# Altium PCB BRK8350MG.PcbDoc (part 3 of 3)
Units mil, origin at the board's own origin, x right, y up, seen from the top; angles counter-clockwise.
Board outline 8858.27 x 5511.81 mil, 6 copper layers (L1-TOP, L2-GND, L3-PWR, L4-PWR, L5-GND, L6-BOT), stack 81.526 mil thick; 49 components, 350 nets, 1087 pads, 250 vias.
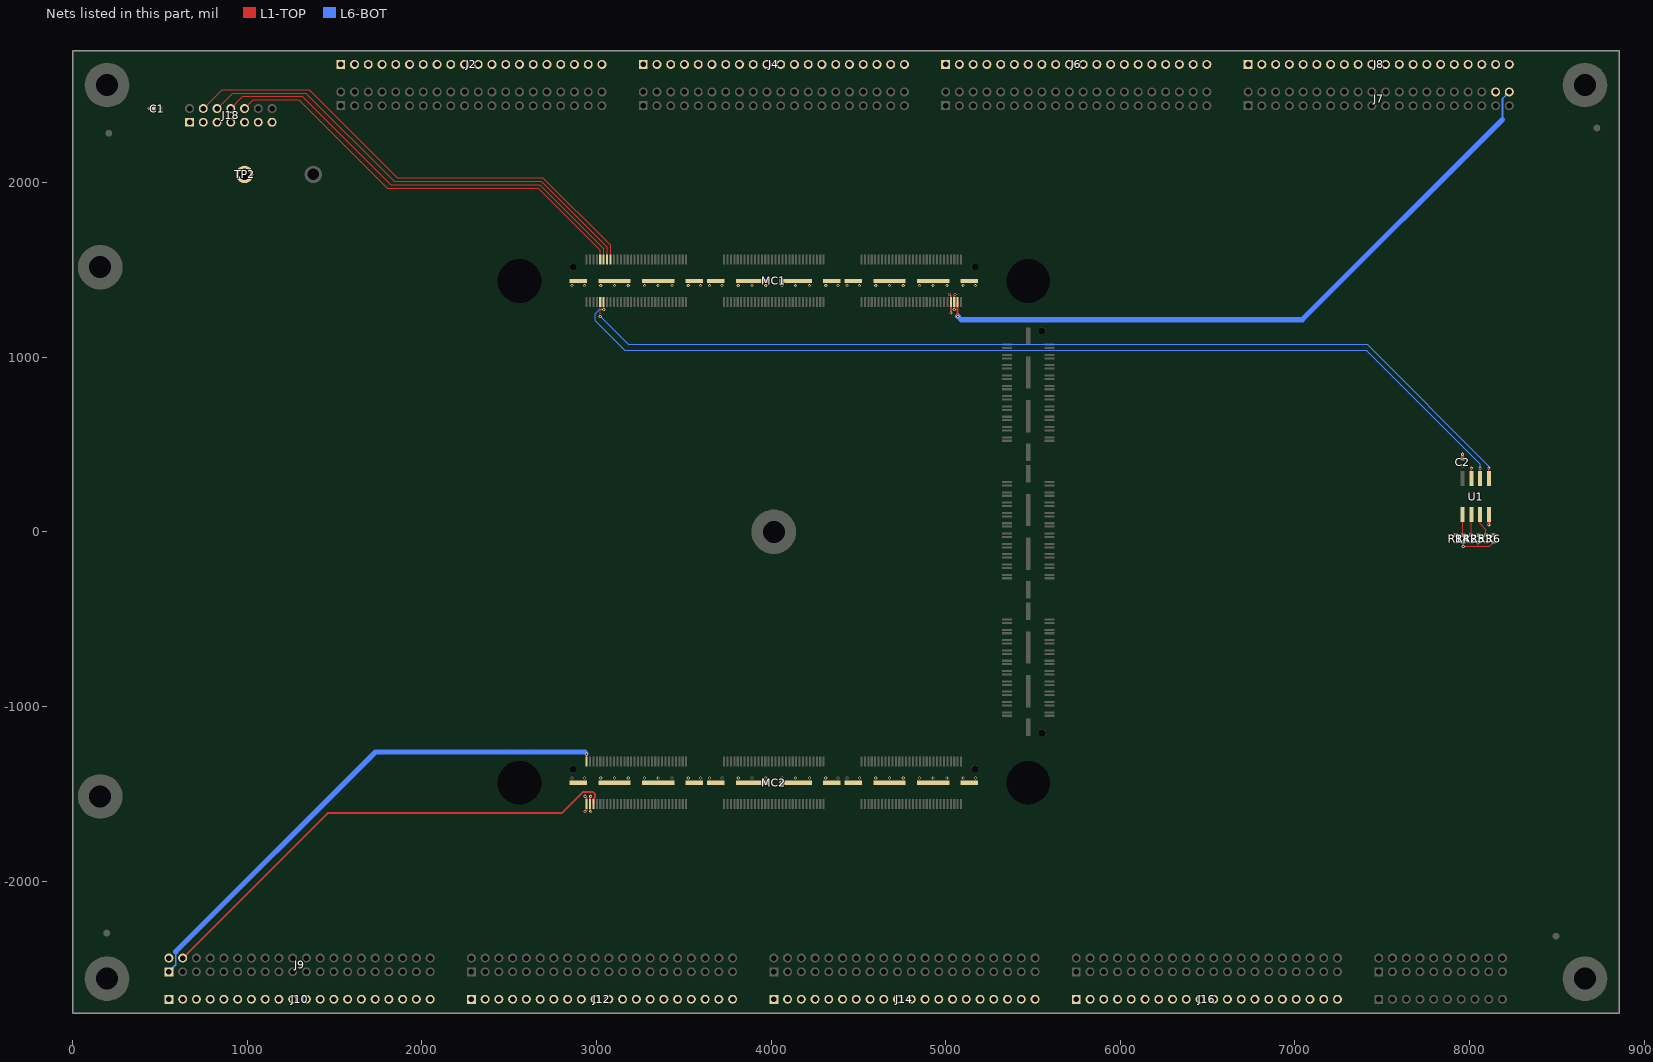
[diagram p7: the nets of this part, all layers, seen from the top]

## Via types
v1: diameter 18, hole 10, L1-TOP to L6-BOT, tented both sides, 250 vias

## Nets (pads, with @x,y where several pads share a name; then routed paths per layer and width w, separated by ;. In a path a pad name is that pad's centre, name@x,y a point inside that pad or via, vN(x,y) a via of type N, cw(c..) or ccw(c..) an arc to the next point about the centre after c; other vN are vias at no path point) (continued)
DGND: C1.1 C2.1 J2.1 J2.2 J2.3 J2.4 J2.5 J2.6 J2.7 J2.8 J2.9 J2.10 J2.11 J2.12 J2.13 J2.14 J2.15 J2.16 J2.17 J2.18 J2.19 J2.20 J4.1 J4.2 J4.3 J4.4 J4.5 J4.6 J4.7 J4.8 J4.9 J4.10 J4.11 J4.12 J4.13 J4.14 J4.15 J4.16 J4.17 J4.18 J4.19 J4.20 J6.1 J6.2 J6.3 J6.4 J6.5 J6.6 J6.7 J6.8 J6.9 J6.10 J6.11 J6.12 J6.13 J6.14 J6.15 J6.16 J6.17 J6.18 J6.19 J6.20 J8.1 J8.2 J8.3 J8.4 J8.5 J8.6 J8.7 J8.8 J8.9 J8.10 J8.11 J8.12 J8.13 J8.14 J8.15 J8.16 J8.17 J8.18 J8.19 J8.20 J10.1 J10.2 J10.3 J10.4 J10.5 J10.6 J10.7 J10.8 J10.9 J10.10 J10.11 J10.12 J10.13 J10.14 J10.15 J10.16 J10.17 J10.18 J10.19 J10.20 J12.1 J12.2 J12.3 J12.4 J12.5 J12.6 J12.7 J12.8 J12.9 J12.10 J12.11 J12.12 J12.13 J12.14 J12.15 J12.16 J12.17 J12.18 J12.19 J12.20 J14.1 J14.2 J14.3 J14.4 J14.5 J14.6 J14.7 J14.8 J14.9 J14.10 J14.11 J14.12 J14.13 J14.14 J14.15 J14.16 J14.17 J14.18 J14.19 J14.20 J16.1 J16.2 J16.3 J16.4 J16.5 J16.6 J16.7 J16.8 J16.9 J16.10 J16.11 J16.12 J16.13 J16.14 J16.15 J16.16 J16.17 J16.18 J16.19 J16.20 J18.1@669.29,2345.94 J18.3@748.03,2345.94 J18.5@826.77,2345.94 J18.7@905.51,2345.94 J18.9@984.25,2345.94 J18.11 J18.13 MC1.0 MC2.0 R4.1 R5.1 R6.1 TP2.1 U1.4 U1.7 | length 403.6
  L1-TOP w5: v1(7964.53,-83.17) 8051,-83.17 ; U1.7@8010.96,304.78 v1(8010.96,364.78) ; R5.1@8051.14,-58.17 8051.14,-83.03 8051,-83.17 ; R6.1@8137.76,-58.17 8112.76,-83.17 8051,-83.17
  L1-TOP w11: v1(438.57,2424.44) C1.1@463.57,2424.44 ; v1(7964.53,-83.17) R4.1@7964.53,-58.17
  L1-TOP w18: C2.1@7961,419.16 v1(7961,444.16) ; v1(8110.96,40.06) U1.4@8110.96,100.06
  other v1: 2860.45,-1409.99 2931.31,-1409.99 3024.62,-1409.99 3103.36,-1409.99 3182.1,-1409.99 3274.62,-1409.99 3353.36,-1409.99 3432.1,-1409.99 3525.41,-1409.99 3596.28,-1409.99 3647.85,-1409.99 3718.72,-1409.99 3812.02,-1409.99 3890.76,-1409.99 3969.5,-1409.99 4062.02,-1409.99 4140.76,-1409.99 4219.5,-1409.99 4312.81,-1409.99 4383.68,-1409.99 4435.25,-1409.99 4506.12,-1409.99 4599.43,-1409.99 4678.17,-1409.99 4756.91,-1409.99 4849.43,-1409.99 4928.17,-1409.99 5006.91,-1409.99 5100.21,-1409.99 5171.08,-1409.99 2860.45,1410.02 2931.31,1410.02 3024.62,1410.02 3103.36,1410.02 3182.1,1410.02 3274.62,1410.02 3353.36,1410.02 3432.1,1410.02 3525.41,1410.02 3596.28,1410.02 3647.85,1410.02 3718.72,1410.02 3812.02,1410.02 3890.76,1410.02 3969.5,1410.02 4062.02,1410.02 4140.76,1410.02 4219.5,1410.02 4312.81,1410.02 4383.68,1410.02 4435.25,1410.02 4506.12,1410.02 4599.43,1410.02 4678.17,1410.02 4756.91,1410.02 4849.43,1410.02 4928.17,1410.02 5006.91,1410.02 5100.21,1410.02 5171.08,1410.02
FPGA_JTAG_TCK: J18.6@826.77,2424.69 MC1.13 | length 2708.7
  L1-TOP w5: J18.6@826.77,2424.69 915.35,2513.27 1335.16,2513.27 1840.55,2007.87 2684.13,2007.87 3061.04,1630.96 MC1.13@3061.04,1558.68
FPGA_JTAG_TDI: J18.10@984.25,2424.69 MC1.9 | length 2469.5
  L1-TOP w5: J18.10@984.25,2424.69 1033.46,2473.9 1295.79,2473.9 1801.18,1968.5 2667.5,1968.5 3021.67,1614.33 MC1.9@3021.67,1558.68
FPGA_JTAG_TDO: J18.8@905.51,2424.69 MC1.11 | length 2589.1
  L1-TOP w5: J18.8@905.51,2424.69 974.41,2493.58 1315.47,2493.58 1820.87,1988.19 2675.81,1988.19 3041.35,1622.65 MC1.11@3041.35,1558.68
FPGA_JTAG_TMS: J18.4@748.03,2424.69 MC1.15 | length 2828.9
  L1-TOP w5: J18.4@748.03,2424.69 856.3,2532.95 1354.84,2532.95 1860.24,2027.56 2693.44,2027.56 3080.72,1640.28 MC1.15@3080.72,1558.68
I2C_SCL: MC1.12 U1.6 | length 5629.4
  L1-TOP w5: v1(3041.35,1273.37) MC1.12@3041.35,1313.37 ; U1.6@8060.96,304.78 v1(8060.96,364.78)
  L6-BOT w5: v1@3041.35,1275.37 3019.37,1275.37 2993,1249 2993,1210 3163,1040 7408,1040 8060.96,387.04 v1(8060.96,364.78)
I2C_SDA: MC1.10 U1.5 | length 5597.1
  L1-TOP w5: v1(3021.67,1233.37) MC1.10@3021.67,1313.37 ; U1.5@8110.96,304.78 v1(8110.96,364.78)
  L6-BOT w5: v1@3021.67,1235.37 3183.04,1074 7414,1074 8110.96,377.04 v1(8110.96,364.78)
NetR1_1: R1.1 R4.2 U1.1 | length 163.6
  L1-TOP w5: R1.1@7921.22,-18.8 R4.2@7964.53,-18.8 7960.96,-15.24 U1.1@7960.96,100.06
NetR2_1: R2.1 R5.2 U1.2 | length 163.5
  L1-TOP w5: U1.2@8010.96,100.06 8010.96,-15.68 R2.1@8007.83,-18.8 R5.2@8051.14,-18.8
NetR3_1: R3.1 R6.2 U1.3 | length 176
  L1-TOP w5: U1.3@8060.96,100.06 8060.96,45.04 8094.45,11.55 R3.1@8094.45,-18.8 R6.2@8137.76,-18.8
VCCBATT: J9.4 MC2.6 | length 2822.4
  L1-TOP w11: J9.4@629.92,-2440.94 1459.87,-1611 2801,-1611 2923,-1489 2979,-1489 2992,-1502 2992,-1519 2982.3,-1528.7 MC2.6@2982.3,-1558.65
VIO1: J7.38 MC1.174 MC1.176 | length 194.6
  L1-TOP w10: v1(5021.54,1359.37) 5029.54,1351.37 MC1.174@5029.54,1315.37 ; MC1.176@5049.23,1315.37 5049.23,1351.37 v1@5057.23,1359.37
  L1-TOP w11: v1(5029.54,1253.37) MC1.174@5029.54,1313.37 ; v1(5049.23,1273.37) MC1.176@5049.23,1313.37
  other v1: 5053.29,1359.37
VIO2: J9.2 MC2.2 MC2.4 | length 189.3
  L1-TOP w10: v1(2934.93,-1602.65) 2942.93,-1594.65 MC2.2@2942.93,-1558.65 2942.93,-1522.65 v1(2934.93,-1514.65) ; v1@2970.61,-1602.65 2962.61,-1594.65 MC2.4@2962.61,-1558.65 2962.61,-1522.65 v1@2970.61,-1514.65
  other v1: 2966.68,-1602.65 2966.68,-1514.65
VREF1: J7.40 MC1.178 | length 3857.5
  L1-TOP w11: v1(5068.91,1233.37) MC1.178@5068.91,1313.37
  L6-BOT w10: 8188.98,2362.2 8188.98,2480.31 J7.40@8228.35,2519.69
  L6-BOT w30: v1@5068.91,1235.37 5089.28,1215 7041.77,1215 8188.98,2362.2
VREF2: J9.1 MC2.1 | length 3005.2
  L1-TOP w5: MC2.1@2942.93,-1313.34 v1(2942.93,-1273.34)
  L6-BOT w10: J9.1@551.18,-2519.69 590.55,-2480.32 590.55,-2404.45
  L6-BOT w20: 2935,-1261 2942.93,-1268.93 v1(2942.93,-1273.34)
  L6-BOT w30: 590.55,-2404.45 1734,-1261 2935,-1261
pads on no net: FID1.FID? FID2.FID? FID3.FID? FID4.FID? J9.6 J18.1@7480.31,-2677.17 J18.2@7559.06,-2677.17 J18.3@7637.8,-2677.17 J18.4@7716.54,-2677.17 J18.5@7795.28,-2677.17 J18.6@7874.02,-2677.17 J18.7@7952.76,-2677.17 J18.8@8031.5,-2677.17 J18.9@8110.24,-2677.17 J18.10@8188.98,-2677.17 J18.12 J18.14 JSO1.1 JSO2.1 JSO3.1 JSO4.1 MC1.14 MC1.16 MC1.180 MC1.MH MC2.MH MC3.0 MC3.1 MC3.2 MC3.3 MC3.4 MC3.5 MC3.6 MC3.7 MC3.8 MC3.9 MC3.10 MC3.11 MC3.12 MC3.13 MC3.14 MC3.15 MC3.16 MC3.17 MC3.18 MC3.19 MC3.20 MC3.21 MC3.22 MC3.23 MC3.24 MC3.25 MC3.26 MC3.27 MC3.28 MC3.29 MC3.30 MC3.31 MC3.32 MC3.33 MC3.34 MC3.35 MC3.36 MC3.37 MC3.38 MC3.39 MC3.40 MC3.41 MC3.42 MC3.43 MC3.44 MC3.45 MC3.46 MC3.47 MC3.48 MC3.49 MC3.50 MC3.51 MC3.52 MC3.53 MC3.54 MC3.55 MC3.56 MC3.57 MC3.58 MC3.59 MC3.60 MC3.61 MC3.62 MC3.63 MC3.64 MC3.65 MC3.66 MC3.67 MC3.68 MC3.69 MC3.70 MC3.71 MC3.72 MC3.73 MC3.74 MC3.75 MC3.76 MC3.77 MC3.78 MC3.79 MC3.80 MC3.81 MC3.82 MC3.83 MC3.84 MC3.85 MC3.86 MC3.87 MC3.88 MC3.89 MC3.90 MC3.91 MC3.92 MC3.93 MC3.94 MC3.95 MC3.96 MC3.97 MC3.98 MC3.99 MC3.100 MC3.101 MC3.102 MC3.103 MC3.104 MC3.105 MC3.106 MC3.107 MC3.108 MC3.109 MC3.110 MC3.111 MC3.112 MC3.113 MC3.114 MC3.115 MC3.116 MC3.117 MC3.118 MC3.119 MC3.120 MC3.MH MH1.1 MH2.1 MH3.1 MH4.1 MH5.1 MH6.1

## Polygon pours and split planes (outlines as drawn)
+VDCIN on L1-TOP "L1_+VDCIN" (solid, pour order 221): 374,2244.09 374,354.33 3010,354.33 3010,1601 2681.87,1929.13 1771.65,1929.13 1456.69,2244.09
+3.3VDD on L1-TOP "L1_+3.3VDD" (solid, pour order 230): 5020,1615 5039,1634 7322,1634 8101,2413 8101,2602 8356,2602 8669,2289 8669,354.33 5112,354.33 5112,1359 5078,1359 5020,1417
VIO2 on L4-PWR "L4_VIO2" (solid, pour order 227): 39.37,-2716.54 4409.45,-2716.54 4409.45,2716.54 39.37,2716.54
VIO1 on L4-PWR "L4_VIO1" (solid, pour order 225): 8818.9,2716.54 4448.82,2716.54 4448.82,-2716.54 8818.9,-2716.54
DGND on L5-GND "L4-DGND" (solid, pour order 202): 19.68,-2736.22 19.68,2736.22 8838.58,2736.22 8838.58,-2736.22
DGND on L2-GND "L2_DGND" (solid, pour order 220): 19.69,-2736.22 19.69,2736.22 8838.58,2736.22 8838.58,-2736.22
+1.8VDD on L3-PWR "L3_+1.8VDD" (solid, pour order 224): 39.37,2716.54 39.37,-2716.54 8818.9,-2716.54 8818.9,2716.54

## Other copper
L1-TOP:
  rectangle net DGND: 2846,1400 2945,1448
  rectangle net DGND: 3012,1400 5185,1449
  rectangle net DGND: 2846,-1449 5185,-1400

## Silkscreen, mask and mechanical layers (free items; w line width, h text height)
Top Silkscreen:
  lines w4.72: 6167.63,1300.63 6167.7,1300.63
  lines w7.87: 413.39,-1673.23 5708.68,-1673.21 5708.68,1673.24 413.39,1673.23
  text "2:Vref" at 651.7,2730.24 h40 r270
  text "4:TMS" at 729.7,2730.24 h40 r270
  text "6:TCK" at 808.7,2730.24 h40 r270
  text "8:TDO" at 885.7,2730.24 h40 r270
  text "10:TDI" at 964.7,2730.24 h40 r270
  text "DGND" at 1362.65,2665.41 h30
  text "DGND" at 3094.93,2665.41 h30
  text "DGND" at 4827.22,2665.41 h30
  text "DGND" at 6559.5,2665.41 h30
  text "DGND" at 8287.22,2663.47 h30
  text "'.Part_Number' / '.PCB_Revision'XX" at 6913.7,-57.76 h40
  text "DGND" at 378.4,-2688.92 h30
  text "DGND" at 2110.68,-2688.92 h30
  text "DGND" at 3842.97,-2688.92 h30
  text "DGND" at 5575.25,-2688.92 h30
  text "DGND" at 7306.22,-2693.97 h30
  text "DGND" at 8247.22,-2693.97 h30
Dimensions:
  text ":::" at 2778.52,2835 h50 r180
  text ":::" at 6154.52,2806 h50
  text ":::" at 8920,1240 h50 r270
  text ":::" at -41,1148.36 h50 r90
  text ":::" at 8926,-1158 h50 r270
  text ":::" at -53,-1222 h50 r90
  text ":::" at 6246.16,-2793 h50 r180
  text ":::" at 2778.52,-2807 h50 r180
Outline:
  the board outline again, w8
Fab Notes:
  drawing of 56 lines, arcs and shapes, not listed
  text "LAYER STACK TABLE" at 5597,6144 h60
  text "M" at 9000.2,6000.12 h91.75
  text "a" at 9061.4,6000.12 h91.75
  text "t" at 9105.92,6000.12 h91.75
  text "e" at 9128.17,6000.12 h91.75
  text "r" at 9172.69,6000.12 h91.75
  text "i" at 9200.51,6000.12 h91.75
  text "a" at 9217.2,6000.12 h91.75
  text "l" at 9261.71,6000.12 h91.75
  text "C" at 9428.48,5896.05 h97.15
  text "o" at 9472.99,5896.05 h97.15
  text "p" at 9517.51,5896.04 h97.15
  text "p" at 9562.02,5896.04 h97.15
  text "e" at 9606.53,5896.05 h97.15
  text "r" at 9651.04,5896.05 h97.15
  text "P" at 8983.51,5894.41 h91.75
  text "r" at 9039.15,5894.41 h91.75
  text "e" at 9066.97,5894.41 h91.75
  text "s" at 9111.49,5894.41 h91.75
  text "s" at 9156,5894.41 h91.75
  text "e" at 9200.51,5894.41 h91.75
  text "d" at 9245.02,5894.41 h91.75
  text "G" at 6680.8,5788.69 h91.75
  text "e" at 6742,5788.69 h91.75
  text "r" at 6786.51,5788.69 h91.75
  text "b" at 6814.33,5788.69 h91.75
  text "e" at 6858.85,5788.69 h91.75
  text "r" at 6903.36,5788.69 h91.75
  text "M" at 8499.61,5788.69 h91.75
  text "a" at 8560.81,5788.69 h91.75
  text "t" at 8605.33,5788.69 h91.75
  text "e" at 8627.58,5788.69 h91.75
  text "r" at 8672.09,5788.69 h91.75
  text "i" at 8699.91,5788.69 h91.75
  text "a" at 8716.61,5788.69 h91.75
  text "l" at 8761.12,5788.69 h91.75
  text "E" at 8800.07,5788.69 h91.75
  text "r" at 8855.71,5788.69 h91.75
  text "T" at 8950.14,5788.69 h91.75
  text "h" at 9000.22,5788.69 h91.75
  text "i" at 9044.73,5788.69 h91.75
  text "c" at 9061.42,5788.69 h91.75
  text "k" at 9105.93,5788.69 h91.75
  text "n" at 9144.88,5788.69 h91.75
  text "e" at 9189.39,5788.69 h91.75
  text "s" at 9233.91,5788.69 h91.75
  text "s" at 9278.42,5788.69 h91.75
  text "T" at 9383.99,5784.77 h97.15
  text "h" at 9422.93,5784.77 h97.15
  text "i" at 9467.45,5784.77 h97.15
  text "c" at 9489.7,5784.77 h97.15
  text "k" at 9523.09,5784.77 h97.15
  text "n" at 9562.04,5784.77 h97.15
  text "e" at 9606.55,5784.77 h97.15
  text "s" at 9651.06,5784.77 h97.15
  text "s" at 9684.44,5784.77 h97.15
  text "C" at 9873.45,5784.77 h97.15
  text "o" at 9917.96,5784.77 h97.15
  text "p" at 9962.48,5784.76 h97.15
  text "p" at 10006.99,5784.76 h97.15
  text "e" at 10051.5,5784.77 h97.15
  text "r" at 10096.01,5784.77 h97.15
  text "L" at 5612.87,5682.97 h91.75
  text "a" at 5657.38,5682.97 h91.75
  text "y" at 5701.89,5682.98 h91.75
  text "e" at 5740.84,5682.97 h91.75
  text "r" at 5785.35,5682.97 h91.75
  text "L" at 5890.98,5682.97 h91.75
  text "a" at 5935.49,5682.97 h91.75
  text "y" at 5980,5682.98 h91.75
  text "e" at 6018.95,5682.97 h91.75
  text "r" at 6063.46,5682.97 h91.75
  text "N" at 6113.54,5682.97 h91.75
  text "a" at 6169.18,5682.97 h91.75
  text "m" at 6213.69,5682.97 h91.75
  text "e" at 6286.02,5682.97 h91.75
  text "L" at 6680.8,5682.97 h91.75
  text "a" at 6725.31,5682.97 h91.75
  text "y" at 6769.82,5682.98 h91.75
  text "e" at 6808.77,5682.97 h91.75
  text "r" at 6853.28,5682.97 h91.75
  text "M" at 7014.52,5682.97 h91.75
  text "a" at 7075.73,5682.97 h91.75
  text "t" at 7120.24,5682.97 h91.75
  text "e" at 7142.5,5682.97 h91.75
  text "r" at 7187.01,5682.97 h91.75
  text "i" at 7214.83,5682.97 h91.75
  text "a" at 7231.52,5682.97 h91.75
  text "l" at 7276.03,5682.97 h91.75
  text "T" at 7314.98,5682.97 h91.75
  text "y" at 7365.06,5682.98 h91.75
  text "p" at 7404.01,5682.98 h91.75
  text "e" at 7448.52,5682.97 h91.75
  text "M" at 7587.42,5682.97 h91.75
  text "a" at 7648.63,5682.97 h91.75
  text "t" at 7693.14,5682.97 h91.75
  text "e" at 7715.39,5682.97 h91.75
  text "r" at 7759.91,5682.97 h91.75
  text "i" at 7787.73,5682.97 h91.75
  text "a" at 7804.42,5682.97 h91.75
  text "l" at 7848.93,5682.97 h91.75
  text "C" at 7887.88,5682.97 h91.75
  text "o" at 7949.08,5682.97 h91.75
  text "n" at 7993.6,5682.97 h91.75
  text "s" at 8038.11,5682.97 h91.75
  text "t" at 8082.62,5682.97 h91.75
  text "r" at 8104.88,5682.97 h91.75
  text "u" at 8132.7,5682.97 h91.75
  text "c" at 8177.21,5682.97 h91.75
  text "t" at 8221.72,5682.97 h91.75
  text "i" at 8243.98,5682.97 h91.75
  text "o" at 8260.67,5682.97 h91.75
  text "n" at 8305.18,5682.97 h91.75
  text "(" at 8549.67,5682.98 h91.75
  text "1" at 8577.49,5682.97 h91.75
  text "G" at 8644.26,5682.97 h91.75
  text "H" at 8705.46,5682.97 h91.75
  text "z" at 8761.1,5682.97 h91.75
  text ")" at 8805.61,5682.98 h91.75
  text "(" at 9033.57,5682.98 h91.75
  text "m" at 9061.39,5682.97 h91.75
  text "i" at 9133.73,5682.97 h91.75
  text "l" at 9150.42,5682.97 h91.75
  text "s" at 9167.11,5682.97 h91.75
  text ")" at 9211.62,5682.98 h91.75
  text "(" at 9450.73,5673.48 h97.15
  text "m" at 9478.55,5673.49 h97.15
  text "i" at 9545.32,5673.49 h97.15
  text "l" at 9567.58,5673.49 h97.15
  text "s" at 9589.83,5673.49 h97.15
  text ")" at 9623.22,5673.48 h97.15
  text "W" at 9795.58,5673.49 h97.15
  text "e" at 9867.92,5673.49 h97.15
  text "i" at 9912.43,5673.49 h97.15
  text "g" at 9934.68,5673.48 h97.15
  text "h" at 9973.63,5673.49 h97.15
  text "t" at 10018.14,5673.49 h97.15
  text "(" at 10062.66,5673.48 h97.15
  text "o" at 10090.48,5673.49 h97.15
  text "z" at 10134.99,5673.49 h97.15
  text ")" at 10168.37,5673.48 h97.15
  text "O" at 5890.98,5516.05 h91.75
  text "v" at 5957.74,5516.05 h91.75
  text "e" at 5996.69,5516.05 h91.75
  text "r" at 6041.2,5516.05 h91.75
  text "l" at 6069.02,5516.05 h91.75
  text "a" at 6085.72,5516.05 h91.75
  text "y" at 6130.23,5516.06 h91.75
  text "T" at 6191.43,5516.05 h91.75
  text "o" at 6241.51,5516.05 h91.75
  text "p" at 6286.02,5516.06 h91.75
  text "G" at 6680.8,5516.05 h91.75
  text "T" at 6742,5516.05 h91.75
  text "O" at 6792.08,5516.05 h91.75
  text "S" at 7014.52,5516.05 h91.75
  text "i" at 7070.16,5516.05 h91.75
  text "l" at 7086.86,5516.05 h91.75
  text "k" at 7103.55,5516.05 h91.75
  text "s" at 7142.5,5516.05 h91.75
  text "c" at 7187.01,5516.05 h91.75
  text "r" at 7231.52,5516.05 h91.75
  text "e" at 7259.34,5516.05 h91.75
  text "e" at 7303.85,5516.05 h91.75
  text "n" at 7348.37,5516.05 h91.75
  text "S" at 5890.98,5404.77 h91.75
  text "o" at 5946.62,5404.77 h91.75
  text "l" at 5991.13,5404.77 h91.75
  text "d" at 6007.82,5404.77 h91.75
  text "e" at 6052.33,5404.77 h91.75
  text "r" at 6096.85,5404.77 h91.75
  text "M" at 6146.92,5404.77 h91.75
  text "a" at 6208.13,5404.77 h91.75
  text "s" at 6252.64,5404.77 h91.75
  text "k" at 6297.15,5404.77 h91.75
  text "T" at 6358.36,5404.77 h91.75
  text "o" at 6408.43,5404.77 h91.75
  text "p" at 6452.94,5404.78 h91.75
  text "G" at 6680.8,5404.77 h91.75
  text "T" at 6742,5404.77 h91.75
  text "S" at 6792.08,5404.77 h91.75
  text "S" at 7014.52,5404.77 h91.75
  text "o" at 7070.16,5404.77 h91.75
  text "l" at 7114.68,5404.77 h91.75
  text "d" at 7131.37,5404.77 h91.75
  text "e" at 7175.88,5404.77 h91.75
  text "r" at 7220.39,5404.77 h91.75
  text "R" at 7270.47,5404.77 h91.75
  text "e" at 7331.67,5404.77 h91.75
  text "s" at 7376.19,5404.77 h91.75
  text "i" at 7420.7,5404.77 h91.75
  text "s" at 7437.39,5404.77 h91.75
  text "t" at 7481.9,5404.77 h91.75
  text "3" at 8644.22,5400.85 h97.15
  text "." at 8683.17,5400.85 h97.15
  text "5" at 8705.43,5400.85 h97.15
  text "1" at 5612.87,5293.49 h91.75
  text "L" at 5890.98,5293.49 h91.75
  text "1" at 5935.49,5293.49 h91.75
  text "-" at 5980,5293.48 h91.75
  text "T" at 6007.82,5293.49 h91.75
  text "O" at 6057.9,5293.49 h91.75
  text "P" at 6124.67,5293.49 h91.75
  text "G" at 6680.8,5293.49 h91.75
  text "T" at 6742,5293.49 h91.75
  text "L" at 6792.08,5293.49 h91.75
  text "C" at 7014.52,5293.49 h91.75
  text "o" at 7075.73,5293.49 h91.75
  text "p" at 7120.24,5293.5 h91.75
  text "p" at 7164.75,5293.5 h91.75
  text "e" at 7209.26,5293.49 h91.75
  text "r" at 7253.78,5293.49 h91.75
  text "1" at 9500.79,5289.57 h97.15
  text "." at 9539.74,5289.57 h97.15
  text "2" at 9561.99,5289.57 h97.15
  text "0" at 9790.02,5289.57 h97.15
  text "." at 9828.97,5289.57 h97.15
  text "5" at 9851.22,5289.57 h97.15
  text "+" at 9906.87,5289.57 h97.15
  text "p" at 9962.51,5289.56 h97.15
  text "l" at 10007.02,5289.57 h97.15
  text "a" at 10029.27,5289.57 h97.15
  text "t" at 10068.22,5289.57 h97.15
  text "i" at 10096.04,5289.57 h97.15
  text "n" at 10118.3,5289.57 h97.15
  text "g" at 10162.81,5289.56 h97.15
  text "P" at 7014.52,5182.21 h91.75
  text "r" at 7070.16,5182.21 h91.75
  text "e" at 7097.98,5182.21 h91.75
  text "p" at 7142.5,5182.22 h91.75
  text "r" at 7187.01,5182.21 h91.75
  text "e" at 7214.83,5182.21 h91.75
  text "g" at 7259.34,5182.22 h91.75
  text "2" at 7587.42,5178.28 h97.15
  text "1" at 7626.37,5178.28 h97.15
  text "1" at 7665.32,5178.28 h97.15
  text "6" at 7704.27,5178.28 h97.15
  text "R" at 7759.91,5178.28 h97.15
  text "C" at 7804.42,5178.28 h97.15
  text "5" at 7848.93,5178.28 h97.15
  text "5" at 7887.88,5178.28 h97.15
  text "4" at 8621.98,5178.28 h97.15
  text "." at 8660.92,5178.28 h97.15
  text "0" at 8683.18,5178.28 h97.15
  text "7" at 8722.13,5178.28 h97.15
  text "4" at 9066.94,5178.28 h97.15
  text "." at 9105.89,5178.28 h97.15
  text "5" at 9128.15,5178.28 h97.15
  text "7" at 9167.1,5178.28 h97.15
  text "2" at 5612.87,5070.93 h91.75
  text "L" at 5890.98,5070.93 h91.75
  text "2" at 5935.49,5070.93 h91.75
  text "-" at 5980,5070.92 h91.75
  text "G" at 6007.82,5070.93 h91.75
  text "N" at 6069.02,5070.93 h91.75
  text "D" at 6124.67,5070.93 h91.75
  text "G" at 6680.8,5070.93 h91.75
  text "1" at 6742,5070.93 h91.75
  text "C" at 7014.52,5070.93 h91.75
  text "o" at 7075.73,5070.93 h91.75
  text "p" at 7120.24,5070.94 h91.75
  text "p" at 7164.75,5070.94 h91.75
  text "e" at 7209.26,5070.93 h91.75
  text "r" at 7253.78,5070.93 h91.75
  text "1" at 9500.79,5067 h97.15
  text "." at 9539.74,5067 h97.15
  text "2" at 9561.99,5067 h97.15
  text "1" at 9979.13,5067 h97.15
  text "C" at 7014.52,4959.65 h91.75
  text "o" at 7075.73,4959.65 h91.75
  text "r" at 7120.24,4959.65 h91.75
  text "e" at 7148.06,4959.65 h91.75
  text "7" at 7587.42,4955.72 h97.15
  text "6" at 7626.37,4955.72 h97.15
  text "2" at 7665.32,4955.72 h97.15
  text "8" at 7704.27,4955.72 h97.15
  text "*" at 7743.21,4955.74 h97.15
  text "4" at 7782.16,4955.72 h97.15
  text "+" at 7837.8,4955.72 h97.15
  text "1" at 7893.44,4955.72 h97.15
  text "0" at 7932.39,4955.72 h97.15
  text "8" at 7971.34,4955.72 h97.15
  text "0" at 8010.29,4955.72 h97.15
  text "*" at 8049.24,4955.74 h97.15
  text "1" at 8088.19,4955.72 h97.15
  text "4" at 8621.98,4955.72 h97.15
  text "." at 8660.92,4955.72 h97.15
  text "2" at 8683.18,4955.72 h97.15
  text "7" at 8722.13,4955.72 h97.15
  text "3" at 9050.26,4955.72 h97.15
  text "2" at 9089.21,4955.72 h97.15
  text "." at 9128.16,4955.72 h97.15
  text "6" at 9150.41,4955.72 h97.15
  text "8" at 9189.36,4955.72 h97.15
  text "3" at 5612.87,4848.37 h91.75
  text "L" at 5890.98,4848.36 h91.75
  text "3" at 5935.49,4848.37 h91.75
  text "-" at 5980,4848.36 h91.75
  text "P" at 6007.82,4848.36 h91.75
  text "W" at 6063.46,4848.36 h91.75
  text "R" at 6146.92,4848.36 h91.75
  text "G" at 6680.8,4848.37 h91.75
  text "2" at 6742,4848.36 h91.75
  text "C" at 7014.52,4848.37 h91.75
  text "o" at 7075.73,4848.37 h91.75
  text "p" at 7120.24,4848.37 h91.75
  text "p" at 7164.75,4848.37 h91.75
  text "e" at 7209.26,4848.37 h91.75
  text "r" at 7253.78,4848.36 h91.75
  text "1" at 9500.79,4844.44 h97.15
  text "." at 9539.74,4844.44 h97.15
  text "2" at 9561.99,4844.44 h97.15
  text "1" at 9979.13,4844.44 h97.15
  text "P" at 7014.52,4737.08 h91.75
  text "r" at 7070.16,4737.08 h91.75
  text "e" at 7097.98,4737.08 h91.75
  text "p" at 7142.5,4737.09 h91.75
  text "r" at 7187.01,4737.08 h91.75
  text "e" at 7214.83,4737.08 h91.75
  text "g" at 7259.34,4737.09 h91.75
  text "2" at 7587.42,4733.16 h97.15
  text "1" at 7626.37,4733.16 h97.15
  text "1" at 7665.32,4733.16 h97.15
  text "6" at 7704.27,4733.16 h97.15
  text "H" at 7743.21,4733.16 h97.15
  text "R" at 7809.98,4733.16 h97.15
  text "C" at 7854.5,4733.16 h97.15
  text "5" at 7899.01,4733.16 h97.15
  text "8" at 7937.96,4733.16 h97.15
  text "4" at 8621.98,4733.16 h97.15
  text "." at 8660.92,4733.16 h97.15
  text "0" at 8683.18,4733.16 h97.15
  text "2" at 8722.13,4733.16 h97.15
  text "4" at 9066.94,4733.16 h97.15
  text "." at 9105.89,4733.16 h97.15
  text "6" at 9128.15,4733.16 h97.15
  text "5" at 9167.1,4733.16 h97.15
  text "4" at 5612.87,4625.8 h91.75
  text "L" at 5890.98,4625.8 h91.75
  text "4" at 5935.49,4625.8 h91.75
  text "-" at 5980,4625.79 h91.75
  text "P" at 6007.82,4625.8 h91.75
  text "W" at 6063.46,4625.8 h91.75
  text "R" at 6146.92,4625.8 h91.75
  text "G" at 6680.8,4625.8 h91.75
  text "3" at 6742,4625.8 h91.75
  text "C" at 7014.52,4625.8 h91.75
  text "o" at 7075.73,4625.8 h91.75
  text "p" at 7120.24,4625.81 h91.75
  text "p" at 7164.75,4625.81 h91.75
  text "e" at 7209.26,4625.8 h91.75
  text "r" at 7253.78,4625.8 h91.75
  text "1" at 9500.79,4621.88 h97.15
  text "." at 9539.74,4621.88 h97.15
  text "2" at 9561.99,4621.88 h97.15
  text "1" at 9979.13,4621.88 h97.15
  text "C" at 7014.52,4514.52 h91.75
  text "o" at 7075.73,4514.52 h91.75
  text "r" at 7120.24,4514.52 h91.75
  text "e" at 7148.06,4514.52 h91.75
  text "7" at 7587.42,4510.6 h97.15
  text "6" at 7626.37,4510.6 h97.15
  text "2" at 7665.32,4510.6 h97.15
  text "8" at 7704.27,4510.6 h97.15
  text "*" at 7743.21,4510.61 h97.15
  text "4" at 7782.16,4510.6 h97.15
  text "+" at 7837.8,4510.6 h97.15
  text "1" at 7893.44,4510.6 h97.15
  text "0" at 7932.39,4510.6 h97.15
  text "8" at 7971.34,4510.6 h97.15
  text "0" at 8010.29,4510.6 h97.15
  text "*" at 8049.24,4510.61 h97.15
  text "1" at 8088.19,4510.6 h97.15
  text "4" at 8621.98,4510.6 h97.15
  text "." at 8660.92,4510.6 h97.15
  text "2" at 8683.18,4510.6 h97.15
  text "7" at 8722.13,4510.6 h97.15
  text "3" at 9050.26,4510.6 h97.15
  text "2" at 9089.21,4510.6 h97.15
  text "." at 9128.16,4510.6 h97.15
  text "6" at 9150.41,4510.6 h97.15
  text "8" at 9189.36,4510.6 h97.15
  text "5" at 5612.87,4403.24 h91.75
  text "L" at 5890.98,4403.24 h91.75
  text "5" at 5935.49,4403.24 h91.75
  text "-" at 5980,4403.23 h91.75
  text "G" at 6007.82,4403.24 h91.75
  text "N" at 6069.02,4403.24 h91.75
  text "D" at 6124.67,4403.24 h91.75
  text "G" at 6680.8,4403.24 h91.75
  text "4" at 6742,4403.24 h91.75
  text "C" at 7014.52,4403.24 h91.75
  text "o" at 7075.73,4403.24 h91.75
  text "p" at 7120.24,4403.25 h91.75
  text "p" at 7164.75,4403.25 h91.75
  text "e" at 7209.26,4403.24 h91.75
  text "r" at 7253.78,4403.24 h91.75
  text "1" at 9500.79,4399.32 h97.15
  text "." at 9539.74,4399.32 h97.15
  text "2" at 9561.99,4399.32 h97.15
  text "1" at 9979.13,4399.32 h97.15
  text "P" at 7014.52,4291.96 h91.75
  text "r" at 7070.16,4291.96 h91.75
  text "e" at 7097.98,4291.96 h91.75
  text "p" at 7142.5,4291.97 h91.75
  text "r" at 7187.01,4291.96 h91.75
  text "e" at 7214.83,4291.96 h91.75
  text "g" at 7259.34,4291.97 h91.75
  text "2" at 7587.42,4288.04 h97.15
  text "1" at 7626.37,4288.04 h97.15
  text "1" at 7665.32,4288.04 h97.15
  text "6" at 7704.27,4288.04 h97.15
  text "R" at 7759.91,4288.04 h97.15
  text "C" at 7804.42,4288.04 h97.15
  text "5" at 7848.93,4288.04 h97.15
  text "5" at 7887.88,4288.04 h97.15
  text "4" at 8621.98,4288.04 h97.15
  text "." at 8660.92,4288.04 h97.15
  text "0" at 8683.18,4288.04 h97.15
  text "7" at 8722.13,4288.04 h97.15
  text "4" at 9066.94,4288.04 h97.15
  text "." at 9105.89,4288.04 h97.15
  text "5" at 9128.15,4288.04 h97.15
  text "7" at 9167.1,4288.04 h97.15
  text "6" at 5612.87,4180.68 h91.75
  text "L" at 5890.98,4180.68 h91.75
  text "6" at 5935.49,4180.68 h91.75
  text "-" at 5980,4180.67 h91.75
  text "B" at 6007.82,4180.68 h91.75
  text "O" at 6063.46,4180.68 h91.75
  text "T" at 6130.23,4180.68 h91.75
  text "G" at 6680.8,4180.68 h91.75
  text "B" at 6742,4180.68 h91.75
  text "L" at 6797.64,4180.68 h91.75
  text "C" at 7014.52,4180.68 h91.75
  text "o" at 7075.73,4180.68 h91.75
  text "p" at 7120.24,4180.69 h91.75
  text "p" at 7164.75,4180.69 h91.75
  text "e" at 7209.26,4180.68 h91.75
  text "r" at 7253.78,4180.68 h91.75
  text "1" at 9500.79,4176.76 h97.15
  text "." at 9539.74,4176.76 h97.15
  text "2" at 9561.99,4176.76 h97.15
  text "0" at 9790.02,4176.76 h97.15
  text "." at 9828.97,4176.76 h97.15
  text "5" at 9851.22,4176.76 h97.15
  text "+" at 9906.87,4176.76 h97.15
  text "p" at 9962.51,4176.75 h97.15
  text "l" at 10007.02,4176.76 h97.15
  text "a" at 10029.27,4176.76 h97.15
  text "t" at 10068.22,4176.76 h97.15
  text "i" at 10096.04,4176.76 h97.15
  text "n" at 10118.3,4176.76 h97.15
  text "g" at 10162.81,4176.75 h97.15
  text "S" at 5890.98,4069.4 h91.75
  text "o" at 5946.62,4069.4 h91.75
  text "l" at 5991.13,4069.4 h91.75
  text "d" at 6007.82,4069.4 h91.75
  text "e" at 6052.33,4069.4 h91.75
  text "r" at 6096.85,4069.4 h91.75
  text "M" at 6146.92,4069.4 h91.75
  text "a" at 6208.13,4069.4 h91.75
  text "s" at 6252.64,4069.4 h91.75
  text "k" at 6297.15,4069.4 h91.75
  text "B" at 6358.36,4069.4 h91.75
  text "o" at 6414,4069.4 h91.75
  text "t" at 6458.51,4069.4 h91.75
  text "t" at 6480.76,4069.4 h91.75
  text "o" at 6503.02,4069.4 h91.75
  text "m" at 6547.53,4069.4 h91.75
  text "G" at 6680.8,4069.4 h91.75
  text "B" at 6742,4069.4 h91.75
  text "S" at 6797.64,4069.4 h91.75
  text "S" at 7014.52,4069.4 h91.75
  text "o" at 7070.16,4069.4 h91.75
  text "l" at 7114.68,4069.4 h91.75
  text "d" at 7131.37,4069.4 h91.75
  text "e" at 7175.88,4069.4 h91.75
  text "r" at 7220.39,4069.4 h91.75
  text "R" at 7270.47,4069.4 h91.75
  text "e" at 7331.67,4069.4 h91.75
  text "s" at 7376.19,4069.4 h91.75
  text "i" at 7420.7,4069.4 h91.75
  text "s" at 7437.39,4069.4 h91.75
  text "t" at 7481.9,4069.4 h91.75
  text "3" at 8644.22,4065.47 h97.15
  text "." at 8683.17,4065.47 h97.15
  text "5" at 8705.43,4065.47 h97.15
  text "O" at 5890.98,3958.12 h91.75
  text "v" at 5957.74,3958.12 h91.75
  text "e" at 5996.69,3958.12 h91.75
  text "r" at 6041.2,3958.12 h91.75
  text "l" at 6069.02,3958.12 h91.75
  text "a" at 6085.72,3958.12 h91.75
  text "y" at 6130.23,3958.13 h91.75
  text "B" at 6191.43,3958.12 h91.75
  text "o" at 6247.07,3958.12 h91.75
  text "t" at 6291.59,3958.12 h91.75
  text "t" at 6313.84,3958.12 h91.75
  text "o" at 6336.1,3958.12 h91.75
  text "m" at 6380.61,3958.12 h91.75
  text "G" at 6680.8,3958.12 h91.75
  text "B" at 6742,3958.12 h91.75
  text "O" at 6797.64,3958.12 h91.75
  text "S" at 7014.52,3958.12 h91.75
  text "i" at 7070.16,3958.12 h91.75
  text "l" at 7086.86,3958.12 h91.75
  text "k" at 7103.55,3958.12 h91.75
  text "s" at 7142.5,3958.12 h91.75
  text "c" at 7187.01,3958.12 h91.75
  text "r" at 7231.52,3958.12 h91.75
  text "e" at 7259.34,3958.12 h91.75
  text "e" at 7303.85,3958.12 h91.75
  text "n" at 7348.37,3958.12 h91.75
  text "NOTES: /  / 1. MATERIAL: /    IT-180A or equivalent /    Surface finish: ENIG /    Overall thickness: 90 mils +/-10% /  / 2. Fabricate to IPC-6012 (latest revision), Class II /  / 3. SOLDER RESIST: Glossy blue LPI applied over bare copper or gold/nickel plating /  / 4. SILKSCREEN: White /  / 5. LOT CODE IDENTIFICATION: /    Supplier must add identifier and lot code date to silkscreen. /    LOT CODE DATE FORMAT: YYWW (YY = 2-digit year, WW = 2-digit week) /  / 6. Drill sizes are finished size after plating /  / 7. 100% electrical bare board test required for continuity /  / 8. IMPEDANCE CONTROL: Not required /  / 9. PANELIZATION: /    1 piece per array /    Tab routing required. Tab locations indicated by ::: (see Dimensions Gerber layer) /    0.25-inch rails on all sides /  / 10. POFV: Plated over filled vias are not required /  / 11. ROHS: Fabricate to meet EU RoHS directive. Supplier must add lead-free marking in silkscreen. /  / 12. UL certification mark required (94V-0) /  / 13. Remove all non-functional pads from internal layers" at -479,3347 h50
Assy Notes Top:
Drill Drawing:
  circle w8: c9570.09,1917.78 r27.78
  lines w8: 9542.31,1320.56 9597.86,1320.56 9570.09,1265 9542.31,1320.56 ; 9542.31,1390 9597.86,1390 9597.86,1445.56 9542.31,1445.56 9542.31,1390 ; 9542.31,1528.89 9556.2,1528.89 9570.09,1515 9583.97,1528.89 9597.86,1528.89 9583.97,1542.78 9597.86,1556.67 9583.97,1556.67 9570.09,1570.56 9556.2,1556.67 9542.31,1556.67 9556.2,1542.78 9542.31,1528.89 ; 9542.31,1653.89 9556.2,1653.89 9556.2,1640 9583.97,1640 9583.97,1653.89 9597.86,1653.89 9597.86,1681.67 9583.97,1681.67 9583.97,1695.56 9556.2,1695.56 9556.2,1681.67 9542.31,1681.67 9542.31,1653.89 ; 9542.31,1765 9570.09,1778.89 9597.86,1765 9583.97,1792.78 9597.86,1820.56 9570.09,1806.67 9542.31,1820.56 9556.2,1792.78 9542.31,1765
  lines w10: 9492.59,1227.5 14900.05,1227.5 ; 9492.59,1977.5 14900.05,1977.5 ; 9950.58,1102.5 9950.58,2102.5 ; 10449.78,1102.5 10449.78,2102.5 ; 11570.05,1102.5 11570.05,2102.5 ; 11990.55,1102.5 11990.55,2102.5 ; 12980.86,1102.5 12980.86,2102.5 ; 13471.34,1102.5 13471.34,2102.5 ; 14371.68,1102.5 14371.68,2102.5 ; 9492.59,1102.5 14900.05,1102.5 14900.05,2102.5 9492.59,2102.5 9492.59,1102.5
  text "DRILL TABLE" at 9510,2157 h60
  text "Symbol" at 9567.59,2015 h60
  text "Count" at 9988.08,2015 h60
  text "Finished Hole Size" at 10487.28,2015 h60
  text "Plated" at 11607.55,2015 h60
  text "Drill Layer Pair" at 12028.05,2015 h60
  text "Via/Pad" at 13018.36,2015 h60
  text "Hole Tolerance" at 13508.84,2015 h60
  text "Comment" at 14409.18,2015 h60
  text "250" at 9988.08,1890 h50
  text "10.00mil (0.254mm)" at 10487.28,1890 h50
  text "PTH" at 11607.55,1890 h50
  text "L1-TOP - L6-BOT" at 12028.05,1890 h50
  text "Via" at 13018.36,1890 h50
  text "+/-3.00mil" at 13508.84,1890 h50
  text "524" at 9988.08,1765 h50
  text "31.50mil (0.800mm)" at 10487.28,1765 h50
  text "PTH" at 11607.55,1765 h50
  text "L1-TOP - L6-BOT" at 12028.05,1765 h50
  text "Pad" at 13018.36,1765 h50
  text "+/-3.15mil" at 13508.84,1765 h50
  text "6" at 9988.08,1640 h50
  text "40.16mil (1.020mm)" at 10487.28,1640 h50
  text "NPTH" at 11607.55,1640 h50
  text "L1-TOP - L6-BOT" at 12028.05,1640 h50
  text "Pad" at 13018.36,1640 h50
  text "+/-3.00mil" at 13508.84,1640 h50
  text "2" at 9988.08,1515 h50
  text "65.00mil (1.651mm)" at 10487.28,1515 h50
  text "PTH" at 11607.55,1515 h50
  text "L1-TOP - L6-BOT" at 12028.05,1515 h50
  text "Pad" at 13018.36,1515 h50
  text "+/-3.00mil" at 13508.84,1515 h50
  text "7" at 9988.08,1390 h50
  text "125.98mil (3.200mm)" at 10487.28,1390 h50
  text "PTH" at 11607.55,1390 h50
  text "L1-TOP - L6-BOT" at 12028.05,1390 h50
  text "Pad" at 13018.36,1390 h50
  text "+/-3.00mil" at 13508.84,1390 h50
  text "4" at 9988.08,1265 h50
  text "250.00mil (6.350mm)" at 10487.28,1265 h50
  text "NPTH" at 11607.55,1265 h50
  text "L1-TOP - L6-BOT" at 12028.05,1265 h50
  text "Pad" at 13018.36,1265 h50
  text "+/-3.00mil" at 13508.84,1265 h50
  text "Press-fit" at 14409.18,1265 h50
  text "793 Total" at 9988.08,1140 h50
Doc-Assy-Top:
  lines w5.43: -574.46,-2438.53 -357.09,-2438.53 ; -574.46,-129 -357.09,-129 ; -574.46,2180.53 -357.09,2180.53 ; 2196.97,-4530.68 2196.97,-4313.32 ; 2196.97,4055.32 2196.97,4272.68 ; 5185.77,-4530.68 5185.77,-4313.32 ; 5185.77,4055.32 5185.77,4272.68 ; 6055.24,-4530.68 10946,-4530.68 ; 7472.11,-4313.02 7472.11,-3538.36 10727.73,-3538.36 ; 7472.11,-4051.6 10727.73,-4051.6 ; 7963.42,-4313.02 7963.42,-4051.6 ; 8174.57,-4530.68 8174.57,-4313.32 ; 8174.57,4055.32 8174.57,4272.68 ; 8725.66,-4313.02 8725.66,-4051.6 ; 8878.06,-4051.27 8878.06,-3538.36 ; 9852.45,-4313.02 9852.45,-4051.6 ; 10728.63,-2438.53 10946,-2438.53 ; 10728.63,-129 10946,-129 ; 10728.63,2180.53 10946,2180.53 ; 10946,-4530.68 10946,4272.68 -574.46,4272.68 -574.46,-4530.68 10946,-4530.68 ; -357.09,-4313.32 10728.63,-4313.32 10728.63,4055.32 -357.09,4055.32 -357.09,-4313.32
  text "1" at 676.86,4129.38 h76.08
  text "2" at 3666.38,4129.38 h76.08
  text "3" at 6649.74,4129.38 h76.08
  text "4" at 9639.64,4129.38 h76.08
  text "A" at -496.37,3236.93 h76.08
  text "A" at 10813.57,3236.93 h76.08
  text "B" at -496.37,927.4 h76.08
  text "B" at 10813.57,927.4 h76.08
  text "C" at -496.37,-1382.12 h76.08
  text "C" at 10813.57,-1382.12 h76.08
  text "TITLE:" at 7556.48,-3623.9 h48.89
  text "Opal Kelly" at 8963.6,-3658.12 h76.04
  text "D" at -496.37,-3686.21 h76.08
  text "D" at 10813.57,-3686.21 h76.08
  text "13500 SW 72nd Ave Suite 100" at 8963.6,-3786.43 h76.04
  text "Portland, OR 97223" at 8963.6,-3893.35 h76.04
  text "'.Part_Number' / Assembly Drawing" at 7591.65,-3895.18 h76.04
  text "www.opalkelly.com" at 8963.6,-4000.28 h76.04
  text "(Top)" at 7591.65,-4019.03 h76.04
  text "REV:" at 7532.59,-4124.03 h48.89
  text "SIZE:" at 8029.7,-4124.03 h48.89
  text "ENGINEER:" at 8791.94,-4124.03 h48.89
  text "DATE:" at 9918.73,-4124.03 h48.89
  text "'.PCB_Revision'XX" at 7598.87,-4256.6 h76.04
  text "ANSI A" at 8095.98,-4256.6 h76.04
  text "NDK" at 8858.22,-4256.6 h76.04
  text ".PRINT_DATE" at 9985.01,-4256.6 h76.04
  text "1" at 676.86,-4463.46 h76.08
  text "2" at 3666.38,-4463.46 h76.08
  text "3" at 6649.74,-4463.46 h76.08
  text "4" at 9639.64,-4463.46 h76.08
Doc-Assy-Bot:
  lines w5.43: -574.34,-2437.51 -356.97,-2437.51 ; -574.34,-127.94 -356.97,-127.94 ; -574.34,2181.64 -356.97,2181.64 ; -356.07,-4050.62 2899.62,-4050.62 ; -356.07,-3537.38 2899.62,-3537.38 2899.62,-4312.05 ; 519.24,-4312.05 519.24,-4050.62 ; 1493.65,-4050.3 1493.65,-3537.38 ; 1646.05,-4312.05 1646.05,-4050.62 ; 2197.15,-4529.72 2197.15,-4312.35 ; 2197.15,4056.47 2197.15,4273.84 ; 2408.31,-4312.05 2408.31,-4050.62 ; 4316.53,-4529.72 -574.34,-4529.72 ; 5186.02,-4529.72 5186.02,-4312.35 ; 5186.02,4056.47 5186.02,4273.84 ; 8174.88,-4529.72 8174.88,-4312.35 ; 8174.88,4056.47 8174.88,4273.84 ; 10729,-2437.51 10946.37,-2437.51 ; 10729,-127.94 10946.37,-127.94 ; 10729,2181.64 10946.37,2181.64 ; -574.34,-4529.72 -574.34,4273.84 10946.37,4273.84 10946.37,-4529.72 -574.34,-4529.72 ; -356.97,-4312.35 -356.97,4056.47 10729,4056.47 10729,-4312.35 -356.97,-4312.35
  text "4" at 732.05,4130.54 h76.08
  text "3" at 3722.02,4130.54 h76.08
  text "2" at 6705.45,4130.54 h76.08
  text "1" at 9695.03,4130.54 h76.08
  text "A" at -441.9,3238.07 h76.08
  text "A" at 10868.28,3238.07 h76.08
  text "B" at -441.9,928.49 h76.08
  text "B" at 10868.28,928.49 h76.08
  text "C" at -441.9,-1381.09 h76.08
  text "C" at 10868.28,-1381.09 h76.08
  text "TITLE:" at 2815.25,-3622.92 h48.89
  text "Opal Kelly" at 1408.11,-3657.13 h76.05
  text "D" at -441.9,-3685.23 h76.08
  text "D" at 10868.28,-3685.23 h76.08
  text "13500 SW 72nd Ave Suite 100" at 1408.11,-3785.44 h76.05
  text "Portland, OR 97223" at 1408.11,-3892.37 h76.05
  text "'.Part_Number' / Assembly Drawing" at 2780.09,-3894.2 h76.05
  text "www.opalkelly.com" at 1408.11,-3999.3 h76.05
  text "(Bottom)" at 2780.09,-4018.05 h76.05
  text "DATE:" at 452.95,-4123.06 h48.89
  text "ENGINEER:" at 1579.77,-4123.06 h48.89
  text "SIZE:" at 2342.03,-4123.06 h48.89
  text "REV:" at 2839.15,-4123.06 h48.89
  text ".PRINT_DATE" at 386.67,-4255.63 h76.05
  text "NDK" at 1513.49,-4255.63 h76.05
  text "ANSI A" at 2275.74,-4255.63 h76.05
  text "'.PCB_Revision'XX" at 2772.87,-4255.63 h76.05
  text "4" at 732.05,-4462.5 h76.08
  text "3" at 3722.02,-4462.5 h76.08
  text "2" at 6705.45,-4462.5 h76.08
  text "1" at 9695.03,-4462.5 h76.08
Assy Top:
  text "NOTES /  / 1. JSO1-JSO4 ARE PRESS-FIT ATTACHED TO THE TOP SIDE OF THE PCB. THE MATING JSO HARDWARE MUST BE ATTACHED TO THE PRESS-FIT PIECE AFTER ASSEMBLY." at -44,3437 h50
Doc-Fab:
  lines w5: 10771,-3272.14 10771,-2216 15310.19,-2216 ; 10771,-2406 12531,-2406 ; 10771,-2296 12531,-2296 ; 11191,-3272.14 11191,-2216 ; 12531,-3272.14 12531,-2216 ; 12531,-3076 15311,-3076 ; 12531,-2636 15310.19,-2636 ; 13091,-3272.14 13091,-3076 ; 13771,-3076 13771,-2636 ; 14421,-3272.14 14421,-3076
  lines w5.49: -952.83,-883.82 -733.05,-883.82 ; -952.83,1726.12 -733.05,1726.12 ; -952.83,4336.06 -733.05,4336.06 ; 1794.47,-3493.76 1794.47,-3273.97 ; 1794.47,6726.22 1794.47,6946 ; 4541.78,-3493.76 4541.78,-3273.97 ; 4541.78,6726.22 4541.78,6946 ; 7289.08,-3493.76 7289.08,-3273.97 ; 7289.08,6726.22 7289.08,6946 ; 10036.39,-3493.76 10036.39,-3273.97 ; 10036.39,6726.22 10036.39,6946 ; 12783.69,-3493.76 12783.69,-3273.97 ; 12783.69,6726.22 12783.69,6946 ; 15311.22,-883.82 15531,-883.82 ; 15311.22,1726.12 15531,1726.12 ; 15311.22,4336.06 15531,4336.06 ; -952.83,-3493.76 -952.83,6946 15531,6946 15531,-3493.76 -952.83,-3493.76 ; -733.05,-3273.97 -733.05,6726.22 15311.22,6726.22 15311.22,-3273.97 -733.05,-3273.97
  text "1" at 400.31,6803.14 h76.92
  text "2" at 3142.85,6803.14 h76.92
  text "3" at 5878.45,6803.14 h76.92
  text "4" at 8633.08,6803.14 h76.92
  text "5" at 11379.27,6803.14 h76.92
  text "6" at 14132.07,6803.14 h76.92
  text "A" at -870.41,5547.07 h76.92
  text "A" at 15393.63,5547.07 h76.92
  text "B" at -870.41,2931.64 h76.92
  text "B" at 15393.63,2931.64 h76.92
  text "C" at -870.41,321.7 h76.92
  text "C" at 15393.63,321.7 h76.92
  text "REVISION:" at 10800,-2276 h40
  text "DESCRIPTION:" at 11230,-2276 h40
  text "D" at -870.41,-2282.75 h76.92
  text "D" at 15393.63,-2282.75 h76.92
  text "PART NUMBER:" at 12611,-2356 h75
  text "AXX" at 10801,-2376 h50
  text "Initial Release" at 11231,-2376 h50
  text "'.Part_Number'-PCB-'.PCB_Revision'XX" at 12631,-2636 h130
  text "TITLE:" at 12591,-2716 h40
  text "Opal Kelly" at 13831,-2736 h60
  text "13500 SW 72nd Ave Suite 100" at 13831,-2836 h60
  text "Portland, OR 97223" at 13831,-2936 h60
  text "'.Part_Number' / Fabrication Drawing" at 12631,-3016 h60
  text "www.opalkelly.com" at 13831,-3036 h60
  text "SIZE:" at 12591,-3136 h40
  text "ENGINEER:" at 13151,-3136 h40
  text "DATE:" at 14471,-3136 h40
  text "ANSI A" at 12631,-3236 h60
  text "NDK" at 13191,-3236 h60
  text ".PRINT_DATE" at 14511,-3236 h60
  text "1" at 400.31,-3416.83 h76.92
  text "2" at 3142.85,-3416.83 h76.92
  text "3" at 5878.45,-3416.83 h76.92
  text "4" at 8633.08,-3416.83 h76.92
  text "5" at 11379.27,-3416.83 h76.92
  text "6" at 14132.07,-3416.83 h76.92

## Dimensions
0,-2755.91 to 196.85,2755.91 on Dimensions
0,-2755.91 to 8858.27,-2755.91 on Dimensions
